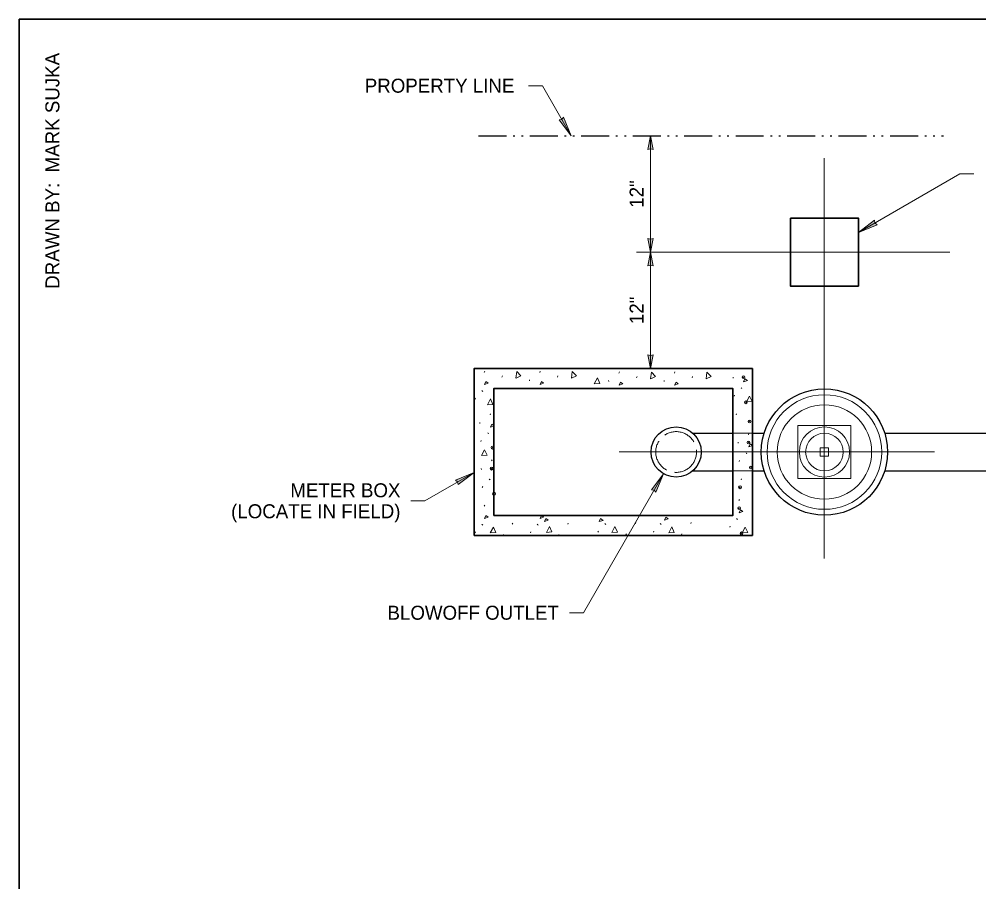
# Model space of a CAD drawing. Extents: x 99860 to 103153, y 99998 to 102077.
# Drawn here: x 99862 to 100960, y 101089 to 102076 of the extents above; entities that cross this region are included whole.
import ezdxf
from ezdxf.enums import TextEntityAlignment as Align

# ---------------------------------------------------------------- set-up
doc = ezdxf.new("R2010")
doc.units = 0
doc.header["$LTSCALE"] = 6.4
doc.header["$PDMODE"] = 32
doc.header["$PDSIZE"] = 3.2
doc.linetypes.add('DASH_DOUBLE_DOT', pattern=[9.2, 5, -1.2, 0.3, -1.2, 0.3, -1.2])
doc.linetypes.add('LONG_DASHED', pattern=[7.5, 6, -1.5])
for name, color, linetype, lineweight in [('1', 7, 'Continuous', 13), ('11', 7, 'Continuous', 13), ('15', 7, 'Continuous', 13), ('17', 7, 'Continuous', 35), ('20', 7, 'Continuous', 13), ('6', 7, 'Continuous', 25)]:
    doc.layers.add(name, color=color, linetype=linetype, lineweight=lineweight)
doc.layers.add('62', color=7, linetype='Continuous')

msp = doc.modelspace()

# ---------------------------------------------------------------- hatches: boundary and pattern name
at = {"layer": '15'}
for points in [[(100493.761, 101942.044), (100484.931, 101963.307), (100482.874, 101960.9), (100479.761, 101960.322)], [(100584.501, 101942.044), (100587.585, 101926.319), (100584.501, 101927.047), (100581.417, 101926.319)], [(100822.313, 101831.584), (100840.591, 101845.583), (100841.167, 101842.469), (100843.576, 101840.413)], [(100584.501, 101808.982), (100587.585, 101824.707), (100584.501, 101823.979), (100581.417, 101824.707)], [(100584.501, 101808.982), (100587.585, 101793.257), (100584.501, 101793.985), (100581.417, 101793.257)], [(100584.501, 101675.882), (100587.585, 101691.607), (100584.501, 101690.879), (100581.417, 101691.607)], [(100382.538, 101557.153), (100361.275, 101548.323), (100363.682, 101546.266), (100364.26, 101543.153)], [(100599.342, 101555.586), (100585.342, 101537.308), (100588.455, 101536.73), (100590.512, 101534.322)]]:
    msp.add_hatch(color=256, dxfattribs=at).paths.add_polyline_path(points)

# ---------------------------------------------------------------- linework, layer by layer
at = {"layer": '1'}
for p, q in [((100394.126, 101671.557), (100394.688, 101672.819)), ((100414.176, 101666.157), (100414.901, 101667.444)), ((100457.663, 101671.557), (100458.101, 101672.819)), ((100477.838, 101666.157), (100478.251, 101667.444)), ((100548.188, 101670.732), (100548.763, 101671.994)), ((100611.726, 101670.732), (100612.163, 101671.994)), ((100382.351, 101662.907), (100382.501, 101661.769)), ((100445.851, 101662.907), (100445.851, 101661.769)), ((100536.413, 101662.082), (100536.576, 101660.944)), ((100568.238, 101665.332), (100568.976, 101666.632)), ((100599.913, 101662.082), (100599.913, 101660.944)), ((100631.901, 101665.332), (100632.313, 101666.632)), ((100678.863, 101666.119), (100679.013, 101664.982)), ((100391.438, 101650.807), (100391.851, 101650.082)), ((100391.851, 101650.519), (100392.426, 101649.832)), ((100687.951, 101654.032), (100688.363, 101653.307)), ((100688.363, 101653.744), (100688.938, 101653.044)), ((100383.488, 101640.982), (100384.051, 101642.119)), ((100680.001, 101644.207), (100680.563, 101645.344)), ((100400.826, 101622.957), (100401.388, 101624.219)), ((100682.276, 101622.957), (100682.838, 101624.219)), ((100389.038, 101614.307), (100389.201, 101613.169)), ((100398.138, 101602.207), (100398.551, 101601.482)), ((100398.551, 101601.919), (100399.113, 101601.232)), ((100390.176, 101592.394), (100390.751, 101593.519)), ((100684.676, 101591.594), (100684.826, 101590.457)), ((100696.451, 101600.257), (100697.013, 101601.519)), ((100402.488, 101570.282), (100403.063, 101571.544)), ((100685.813, 101569.682), (100686.376, 101570.819)), ((100693.763, 101579.507), (100694.176, 101578.782)), ((100694.176, 101579.219), (100694.738, 101578.532)), ((100390.713, 101561.632), (100390.876, 101560.494)), ((100399.813, 101549.532), (100400.226, 101548.807)), ((100400.226, 101549.257), (100400.788, 101548.557)), ((100688.076, 101548.432), (100688.651, 101549.694)), ((100391.851, 101539.719), (100392.426, 101540.857)), ((100685.613, 101524.944), (100686.188, 101526.207)), ((100394.126, 101518.469), (100394.688, 101519.732)), ((100382.351, 101509.819), (100382.501, 101508.682)), ((100682.938, 101504.194), (100683.338, 101503.469)), ((100683.338, 101503.907), (100683.913, 101503.219)), ((100391.438, 101497.719), (100391.851, 101496.994)), ((100391.851, 101497.432), (100392.426, 101496.744)), ((100426.276, 101497.719), (100426.963, 101499.019)), ((100454.813, 101497.719), (100455.388, 101496.994)), ((100455.388, 101497.432), (100455.826, 101496.744)), ((100489.926, 101497.719), (100490.338, 101499.019)), ((100532.188, 101498.544), (100532.588, 101497.819)), ((100532.588, 101498.257), (100533.163, 101497.557)), ((100567.013, 101498.544), (100567.713, 101499.832)), ((100595.563, 101498.544), (100596.126, 101497.819)), ((100596.126, 101498.257), (100596.563, 101497.557)), ((100630.676, 101498.544), (100631.088, 101499.832)), ((100674.976, 101494.369), (100675.551, 101495.507)), ((100383.488, 101487.894), (100384.051, 101489.032)), ((100415.601, 101484.932), (100416.163, 101486.069)), ((100446.988, 101487.894), (100447.551, 101489.032)), ((100479.138, 101484.932), (100479.538, 101486.069)), ((100524.226, 101488.719), (100524.788, 101489.857)), ((100556.338, 101485.757), (100556.913, 101486.882)), ((100587.726, 101488.719), (100588.301, 101489.857)), ((100619.876, 101485.757), (100620.288, 101486.882))]:
    msp.add_line(p, q, dxfattribs=at)
at = {"layer": '1', "lineweight": 35}
msp.add_lwpolyline([(99862, 99999.5), (103151, 99999.5), (103151, 102075.5), (99862, 102075.5)], close=True, dxfattribs=at)
at = {"layer": '1'}
for points in [[(100430.376, 101664.857), (100431.388, 101672.407), (100436.188, 101667.569), (100430.501, 101664.857)], [(100493.913, 101664.857), (100494.888, 101672.407), (100499.726, 101667.569), (100494.038, 101664.857)], [(100584.438, 101664.032), (100585.451, 101671.582), (100590.251, 101666.757), (100584.576, 101664.032)], [(100647.976, 101664.032), (100648.951, 101671.582), (100653.788, 101666.757), (100648.101, 101664.032)], [(100520.051, 101658.544), (100523.626, 101665.207), (100526.313, 101658.957), (100520.213, 101658.544)], [(100397.688, 101634.482), (100401.263, 101641.144), (100404.101, 101634.894), (100397.851, 101634.482)], [(100694.201, 101637.707), (100697.776, 101644.369), (100700.613, 101638.107), (100694.363, 101637.707)], [(100391.001, 101576.257), (100394.563, 101582.919), (100397.413, 101576.657), (100391.163, 101576.257)], [(100401.038, 101487.894), (100404.613, 101494.557), (100407.451, 101488.307), (100401.201, 101487.894)], [(100465.201, 101488.557), (100468.776, 101495.219), (100471.463, 101488.969), (100465.363, 101488.557)], [(100540.113, 101488.407), (100543.676, 101495.069), (100546.513, 101488.819), (100540.263, 101488.407)], [(100605.288, 101488.082), (100608.851, 101494.757), (100611.538, 101488.494), (100605.438, 101488.082)], [(100689.188, 101487.869), (100692.751, 101494.532), (100695.601, 101488.282), (100689.338, 101487.869)]]:
    msp.add_lwpolyline(points, dxfattribs=at)
for points in [[(100394.438, 101657.632), (100395.988, 101661.032), (100398.676, 101659.044)], [(100457.938, 101657.632), (100459.488, 101661.032), (100462.076, 101659.044)], [(100548.513, 101656.807), (100550.051, 101660.219), (100552.738, 101658.232)], [(100612.013, 101656.807), (100613.563, 101660.219), (100616.151, 101658.232)], [(100690.951, 101660.844), (100692.501, 101664.257), (100695.188, 101662.269)], [(100401.138, 101609.032), (100402.688, 101612.444), (100405.363, 101610.457)], [(100696.763, 101586.319), (100698.313, 101589.732), (100701.001, 101587.744)], [(100685.938, 101511.019), (100687.476, 101514.419), (100690.163, 101512.432)], [(100394.438, 101504.544), (100395.988, 101507.944), (100398.676, 101505.957)], [(100457.938, 101504.544), (100459.488, 101507.944), (100462.076, 101505.957)], [(100462.963, 101500.969), (100464.513, 101504.382), (100467.101, 101502.394)], [(100525.801, 101500.782), (100527.351, 101504.194), (100530.038, 101502.207)], [(100600.363, 101502.457), (100601.901, 101505.869), (100604.501, 101503.882)]]:
    msp.add_lwpolyline(points, close=True, dxfattribs=at)
for p in [(100690.763, 101665.932), (100693.513, 101637.257), (100697.651, 101615.407), (100696.576, 101591.407), (100403.688, 101585.444), (100402.626, 101561.444), (100699.326, 101562.732), (100686.813, 101540.094), (100405.363, 101532.769), (100685.738, 101516.094), (100688.488, 101487.419)]:
    msp.add_point(p, dxfattribs=at)
at = {"layer": '11', "lineweight": 35}
msp.add_lwpolyline([(100744.513, 101848.044), (100822.313, 101848.044), (100822.313, 101770.207), (100744.513, 101770.207)], close=True, dxfattribs=at)
at = {"layer": '15'}
for p, q in [((100444.62, 101999.446), (100460.62, 101999.446)), ((100493.761, 101942.044), (100460.62, 101999.446)), ((100584.501, 101942.044), (100584.501, 101808.982)), ((100783.251, 101458.819), (100783.251, 101916.557)), ((100822.311, 101831.583), (100938.242, 101898.516)), ((100938.242, 101898.516), (100954.242, 101898.516)), ((100568.501, 101808.982), (100926.713, 101808.982)), ((100584.501, 101808.982), (100584.501, 101675.882)), ((100548.62, 101580.482), (100909.404, 101580.482)), ((100382.538, 101557.153), (100326.246, 101524.653)), ((100507.551, 101396.6), (100599.342, 101555.586)), ((100310.246, 101524.653), (100326.246, 101524.653)), ((100491.55, 101396.6), (100507.551, 101396.6))]:
    msp.add_line(p, q, dxfattribs=at)
at = {"layer": '15', "linetype": 'DASH_DOUBLE_DOT', "lineweight": 25}
msp.add_line((100387.426, 101942.044), (100919.613, 101942.044), dxfattribs=at)
at = {"layer": '15'}
for points in [[(100493.761, 101942.044), (100484.931, 101963.307), (100482.874, 101960.9), (100479.761, 101960.322)], [(100584.501, 101942.044), (100587.585, 101926.319), (100584.501, 101927.047), (100581.417, 101926.319)], [(100822.313, 101831.584), (100840.591, 101845.583), (100841.167, 101842.469), (100843.576, 101840.413)], [(100584.501, 101808.982), (100587.585, 101824.707), (100584.501, 101823.979), (100581.417, 101824.707)], [(100584.501, 101808.982), (100587.585, 101793.257), (100584.501, 101793.985), (100581.417, 101793.257)], [(100584.501, 101675.882), (100587.585, 101691.607), (100584.501, 101690.879), (100581.417, 101691.607)], [(100382.538, 101557.153), (100361.275, 101548.323), (100363.682, 101546.266), (100364.26, 101543.153)], [(100599.342, 101555.586), (100585.342, 101537.308), (100588.455, 101536.73), (100590.512, 101534.322)]]:
    msp.add_lwpolyline(points, close=True, dxfattribs=at)
at = {"layer": '17'}
for points in [[(100382.538, 101485.019), (100382.538, 101675.882), (100701.063, 101675.882), (100701.063, 101485.019)], [(100405.151, 101507.632), (100405.151, 101653.269), (100678.451, 101653.269), (100678.451, 101507.632)]]:
    msp.add_lwpolyline(points, close=True, dxfattribs=at)
at = {"layer": '6'}
for p, q in [((100632.601, 101601.957), (100678.451, 101601.957)), ((100701.063, 101601.957), (100714.326, 101601.957)), ((100852.438, 101601.957), (101254.613, 101601.957)), ((100632.601, 101558.919), (100678.451, 101558.919)), ((100701.063, 101558.919), (100714.326, 101558.919)), ((100852.438, 101558.919), (101254.201, 101558.919))]:
    msp.add_line(p, q, dxfattribs=at)
at = {"layer": '6', "linetype": 'LONG_DASHED', "lineweight": 13}
for p, q in [((100678.451, 101601.957), (100701.063, 101601.957)), ((100678.451, 101558.919), (100701.063, 101558.919))]:
    msp.add_line(p, q, dxfattribs=at)
at = {"layer": '6', "lineweight": 13}
for points in [[(100753.101, 101610.582), (100753.101, 101550.294), (100813.763, 101550.294), (100813.763, 101610.582)], [(100787.901, 101585.119), (100778.576, 101585.119), (100778.576, 101575.782), (100787.901, 101575.782)]]:
    msp.add_lwpolyline(points, close=True, dxfattribs=at)
at = {"layer": '6'}
for centre, radius in [((100783.4, 101580.439), 72.26), ((100613.691, 101580.439), 28.698)]:
    msp.add_circle(centre, radius, dxfattribs=at)
at = {"layer": '6', "lineweight": 13}
for radius in [65.534, 53.999, 28.698, 21.523]:
    msp.add_circle((100783.4, 101580.439), radius, dxfattribs=at)
at = {"layer": '6', "linetype": 'LONG_DASHED', "lineweight": 13}
msp.add_circle((100613.691, 101580.439), 23.317, dxfattribs=at)

# ---------------------------------------------------------------- texts
at = {"layer": '20'}
for s, p in [('PROPERTY LINE', (100428.623, 101991.446)), ('METER BOX', (100298.25, 101528.653)), ('(LOCATE IN FIELD)', (100298.249, 101504.653)), ('BLOWOFF OUTLET', (100479.555, 101388.6))]:
    msp.add_text(s, height=16, dxfattribs=at).set_placement(p, align=Align.RIGHT)
for p in [(100576.501, 101875.515), (100576.501, 101742.435)]:
    msp.add_text('12"', height=16, rotation=90, dxfattribs=at).set_placement(p, align=Align.CENTER)
at = {"layer": '62'}
msp.add_text('DRAWN BY:  MARK SUJKA', height=16, rotation=90, dxfattribs=at).set_placement((99908, 102037.002), align=Align.RIGHT)

doc.saveas('drawing.dxf')
